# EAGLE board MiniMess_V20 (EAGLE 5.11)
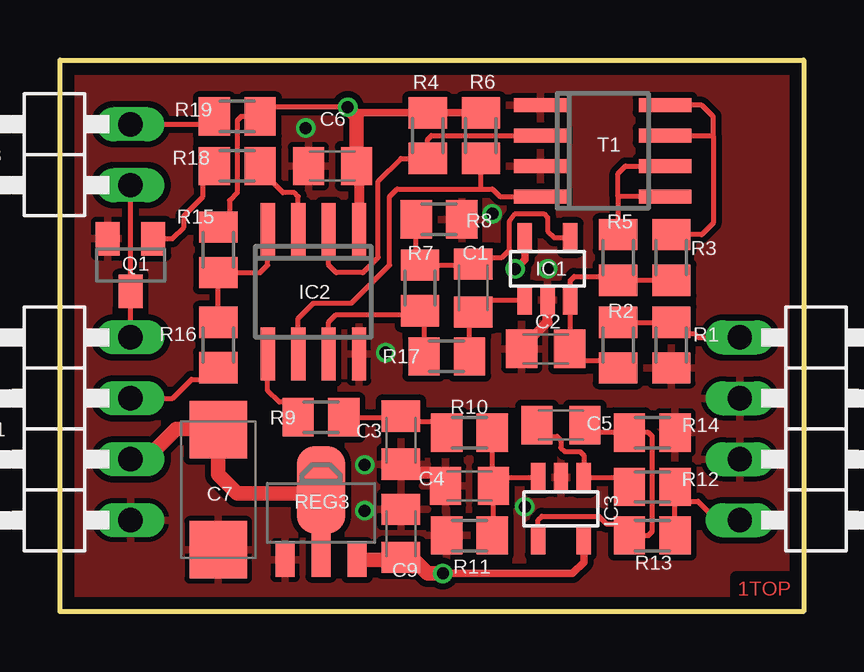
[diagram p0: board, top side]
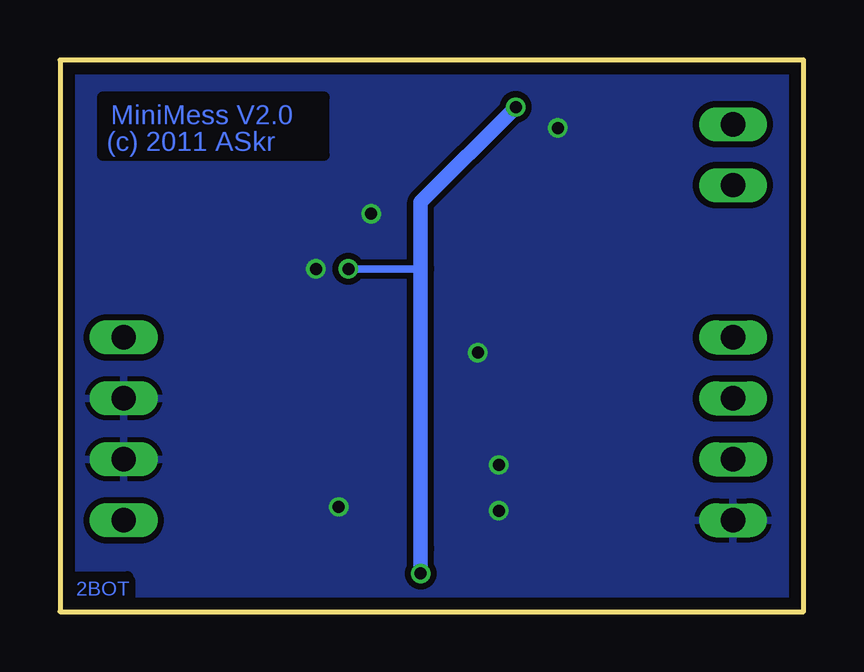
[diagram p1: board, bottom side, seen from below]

Size 31 x 23 mm. Coordinates in mm from the lower left corner, seen from the top.
Outline: 0,0 0,23 31,23 31,0 0,0
Copper layers (1*16): Top 0.035mm / dielectric 1.5mm / Bottom 0.035mm
Design rules "pcb-pool-2009": minimum track width 6mil, minimum drill 12mil, track to track 6mil, track to pad 6mil, pad to pad 6mil, via to via 6mil, smd to smd 6mil, copper to edge 20mil, drill to drill 8mil, minimum pad ring 8mil, minimum via ring 6mil, stop-mask expansion 3mil, vias tented up to drill 0mil, thermal gap 8mil
tRestrict: 2 lines
bRestrict: 6 lines

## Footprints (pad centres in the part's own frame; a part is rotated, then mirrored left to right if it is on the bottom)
C0805K = smd 1.3 x 1.6: 1 -1,0; 2 1,0
SMC_C = smd 2.4 x 2.4: + -2.5,0; - 2.5,0
SOT23-5 = smd 0.6 x 1.2: 1 -0.95,-1.306; 2 0,-1.306; 3 0.95,-1.306; 4 0.95,1.306; 5 -0.95,1.306
SOIC8 = smd 0.6 x 2.2: 1 -1.905,-2.6; 2 -0.635,-2.6; 3 0.635,-2.6; 4 1.905,-2.6; 5 1.905,2.6; 6 0.635,2.6; 7 -0.635,2.6; 8 -1.905,2.6
1X04/90 = drill 1.016 long: 1 -3.81,-3.81; 2 -1.27,-3.81; 3 1.27,-3.81; 4 3.81,-3.81
1X02/90 = drill 1.016 long: 1 -1.27,-3.81; 2 1.27,-3.81
SOT23 = smd 1 x 1.4: 1 -0.95,-1.1; 2 0.95,-1.1; 3 0,1.1
M0805 = smd 1.3 x 1.6: 1 -0.95,0; 2 0.95,0
SOT89 = smd 0.8 x 1.4: 1 -1.499,-1.981; 3 1.499,-1.981 | smd 0.8 x 1.9: 2 0,-1.727 | smd 2.032 x 3.65: 2@1 0,0.94

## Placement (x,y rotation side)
C1  22p  [C0805K]  17.23,13.49 270 top
C2  56p  [C0805K]  20.25,10.95 0 top
C3  100n  [C0805K]  14.22,7.14 90 top
C4  22n  [C0805K]  17.07,5.24 0 top
C5  33p  [C0805K]  20.88,7.78 180 top
C6  100n  [C0805K]  11.36,18.57 0 top
C7  22u;16V  [SMC_C]  6.6,5.08 270 top
C9  2u2  [C0805K]  14.22,3.25 270 top
IC1  OPA336N  [SOT23-5]  20.33,14.29 0 top
IC2  PIC12F683SO8  [SOIC8]  10.56,13.34 180 top
IC3  OPA336N  [SOT23-5]  20.88,4.29 180 top
JP1  [1X04/90]  -0.86,7.62 90 top
JP2  [1X04/90]  32.16,7.62 270 top
JP3  [1X02/90]  -0.86,19.05 90 top
Q1  BC817-40  [SOT23]  2.94,14.45 180 top
R1  10M  [M0805]  25.49,11.11 90 top
R2  1M;1%  [M0805]  23.26,11.11 270 top
R3  200k;1%  [M0805]  25.49,14.76 90 top
R4  1M  [M0805]  15.33,19.84 270 top
R5  100k;1%  [M0805]  23.27,14.76 90 top
R6  1M  [M0805]  17.55,19.84 270 top
R7  110k;1%  [M0805]  15.01,13.49 90 top
R8  180k;1%  [M0805]  15.8,16.35 0 top
R9  10k;1%  [M0805]  10.88,8.1 0 top
R10  100k;1%  [M0805]  17.07,7.46 0 top
R11  180k;1%  [M0805]  17.07,3.18 0 top
R12  100E  [M0805]  24.69,5.2 180 top
R13  110k;1%  [M0805]  24.69,3.18 180 top
R14  180k;1%  [M0805]  24.69,7.46 0 top
R15  1M  [M0805]  6.6,15.08 90 top
R16  100E  [M0805]  6.6,11.11 270 top
R17  100E  [M0805]  16.12,10.64 180 top
R18  10k  [M0805]  7.39,18.57 180 top
R19  10k  [M0805]  7.39,20.64 0 top
REG3  S817A33  [SOT89]  10.88,4.13 0 top
T1  SI9945AEY  [SOIC8]  22.63,19.21 270 top

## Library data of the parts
C1-C6 C9 R1-R19 = rcl
C7 = rcl; SIZE: "C"
IC1 IC3 = burr-brown
IC2 REG3 T1 = Akki
JP1-JP3 = pinhead
Q1 = transistor-npn

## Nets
+3V3: C6.2 C9.2 IC1.5 IC2.1 IC3.5 R4.1 R6.1 R15.2 R19.2 REG3.3
GND: C2.1 C3.1 C4.1 C6.1 C7.- C9.1 IC1.2 IC2.8 IC3.2 JP1.1 JP2.2 JP2.3 Q1.2 R1.1 R8.2 R11.1 R14.2 REG3.1 T1.1 T1.3
IN: JP2.1 R1.2 R2.1
N$1: JP3.2 R19.1
N$2: C2.2 IC1.3 R2.2 R3.1 R5.1
N$3: R3.2 T1.7 T1.8
N$4: C7.+ JP1.2 REG3.2
N$5: IC2.7 R7.1 R17.2
N$6: IC2.2 R4.2 T1.2
N$7: R5.2 T1.5 T1.6
N$8: IC2.4 R15.1 R16.1
N$9: IC2.6 R6.2 T1.4
N$10: C1.2 IC1.1 R17.1
N$11: C1.1 IC1.4 R7.2 R8.1
N$12: IC2.5 R9.1
N$13: C3.2 R9.2 R10.1
N$14: C4.2 IC3.3 R10.2 R11.2
N$15: C5.2 IC3.1 R12.2
N$16: JP2.4 R12.1 R13.1
N$17: C5.1 IC3.4 R13.2 R14.1
N$20: Q1.1 R18.2
N$21: IC2.3 R18.1
RX: JP1.3 R16.2
TX: JP1.4 JP3.1 Q1.3

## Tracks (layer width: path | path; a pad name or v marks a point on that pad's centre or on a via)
+3V3  (via drill 0.5)
  Top 0.203: R15.2 6.75,16.03 7.07,16.35 7.07,17.14 7.39,17.46 7.39,20.48 7.55,20.64 R19.2 8.74,21.03 v11.99,21.03
  Top 0.305: v11.99,21.03 12.39,20.79 R4.1 R6.1 | IC1.5 19.38,14.68 v18.98,14.29 | IC3.5 21.83,2.06 21.36,1.59 v15.96,1.59 | 14.69,1.75 14.53,1.91 14.53,1.94 C9.2
  Top 0.406: IC2.1 12.47,18.46 C6.2
  Top 0.61: v11.99,21.03 12.36,20.61 C6.2 | REG3.3 14.11,2.15 C9.2 14.66,2.25 15.33,1.59 v15.96,1.59
  Bottom 0.305: 15.96,14.29 v18.98,14.29
  Bottom 0.61: v15.96,1.59 15.96,2.62 15.96,14.29 15.96,17.07 v11.99,21.03
GND  (via drill 0.5)
  Top 0.406: C2.1 19.25,11.22 | 20.33,12.78 20.33,12.06 19.54,11.27 19.3,11.27
  Top 0.508: 15.8,5.71 15.72,5.79 14.57,5.79 C3.1
  Top 0.61: C4.1 16.07,5.45 15.8,5.71
  other vias: 12.71,6.11 12.71,4.21 13.58,10.79 10.25,20.16 20.33,14.29 19.38,4.37 18.03,16.59
  pour Bottom (isolate 0.254): 0.16,22.86 30.84,22.86 30.84,0.16 0.16,0.16
  pour Top (isolate 0.254): 0.18,22.86 30.82,22.86 30.82,0.16 0.18,0.16
IN
  Top 0.203: JP2.1 26.6,11.43 26.44,11.59 25.96,11.59 R1.2 R2.1
N$1
  Top 0.203: JP3.2 6.12,20.32 R19.1
N$2
  Top 0.203: R5.1 | R2.2 23.1,10.16 22.79,10.48 21.73,10.48 C2.2 | C2.2 21.2,11 | R5.1 23.11,13.97 21.44,13.97 21.28,13.81 IC1.3 21.28,10.98 C2.2 | R5.1 R3.1
N$3
  Top 0.203: R3.2 26.75,15.71 27.23,16.19 27.23,19.84 | 27.23,19.84 27.23,20.64 26.76,21.11 T1.8 | T1.7 27.23,19.84
  Top 0.305: T1.7 25.17,19.84
N$4
  Top 0.61: JP1.2 3.58,6.35 4.85,7.62 6.56,7.62 C7.+ 6.6,5.71 7.39,4.92 10.09,4.92 10.88,4.13 REG3.2
N$5
  Top 0.203: IC2.7 11.2,12.06 11.52,12.38 14.85,12.38 R7.1 15.17,12.38 R17.2
N$6
  Top 0.203: T1.2 15.49,19.84 15.33,19.68 R4.2 14.22,18.89 13.26,17.94 13.26,14.76 12.63,14.13 11.52,14.13 11.2,14.45 IC2.2
N$7
  Top 0.203: 23.27,16.83 R5.2 | T1.6 23.58,18.57 23.27,18.26 23.27,17.3 | 23.27,17.3 23.27,16.83 | 23.27,16.83 | T1.5 23.27,17.3
N$8
  Top 0.203: R16.1 R15.1 | R15.1 | R15.1 8.35,14.13 8.66,14.45 IC2.4 | IC2.4
N$9
  Top 0.203: 18.34,17.3 T1.4 | R6.2 | IC2.6 9.93,12.22 10.56,12.86 12.15,12.86 13.74,14.45 13.74,17.3 14.06,17.62 17.55,17.62 | IC2.6 | 18.34,17.3 | 18.34,17.3 18.03,17.62 17.55,17.62 | 17.55,17.62 R6.2 | 17.55,17.62
N$10
  Top 0.203: R17.1 17.07,11.99 17.27,12.19 | IC1.1 17.72,12.98 C1.2
  Top 0.305: C1.2 17.23,12.22 17.27,12.19
N$11
  Top 0.203: R7.2 17.18,14.44 C1.1 17.5,14.76 18.42,14.76 18.74,15.08 18.74,16.27 18.98,16.59 20.17,16.59 20.33,16.43 20.33,15.88 20.61,15.59 IC1.4 | R7.2 15.17,14.61 | R8.1 14.85,14.6 R7.2
N$12
  Top 0.203: 9.77,8.26 R9.1 9.3,8.73 9.14,8.73 8.66,9.21 IC2.5
N$13
  Top 0.203: R9.2 14.17,8.1 C3.2 14.49,8.14 14.69,7.94 15.65,7.94 R10.1
N$14
  Top 0.203: R10.2 18.02,5.29 C4.2 | C4.2 18.07,3.23 R11.2 | IC3.3 18.43,5.59 C4.2
N$15
  Top 0.203: R12.2 23.35,5.59 IC3.1 21.83,6.51 21.68,6.67 21.04,6.67 20.88,6.83 20.88,7.14 20.73,7.3 20.25,7.3 20.25,7.41 C5.2 | C5.2
N$16
  Top 0.203: JP2.4 27.39,3.81 26.6,4.6 26.12,4.6 26.12,4.72 R12.1 | R13.1 R12.1 | R12.1
N$17
  Top 0.203: C5.1 21.88,7.46 R14.1 24.54,7.46 24.69,7.3 24.69,3.33 24.54,3.17 R13.2 23.27,3.73 23.19,3.65 22.79,3.65 22.47,3.97 20.09,3.97 19.93,3.81 IC3.4
N$20
  Top 0.203: R18.2 5.96,18.09 5.96,17.3 5.17,16.51 5.17,16.03 4.68,15.55 Q1.1
N$21
  Top 0.203: IC2.3 9.93,17.3 9.77,17.46 9.29,17.46 8.82,17.94 8.82,18.09 R18.1
RX
  Top 0.203: R16.2 6.12,9.68 5.49,9.68 4.69,8.89 JP1.3
TX
  Top 0.203: JP1.4 Q1.3 JP3.1 | JP1.4 | JP3.1

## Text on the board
Top: 1TOP
Bottom: MiniMess V2.0 | (c) 2011 ASkr | 2BOT
tDocu: termination | TX | 1 | A/D in | RX | GND | +UB | GND | GND | D/A out | 1 | (c) ASkr | MiniMess V2.0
